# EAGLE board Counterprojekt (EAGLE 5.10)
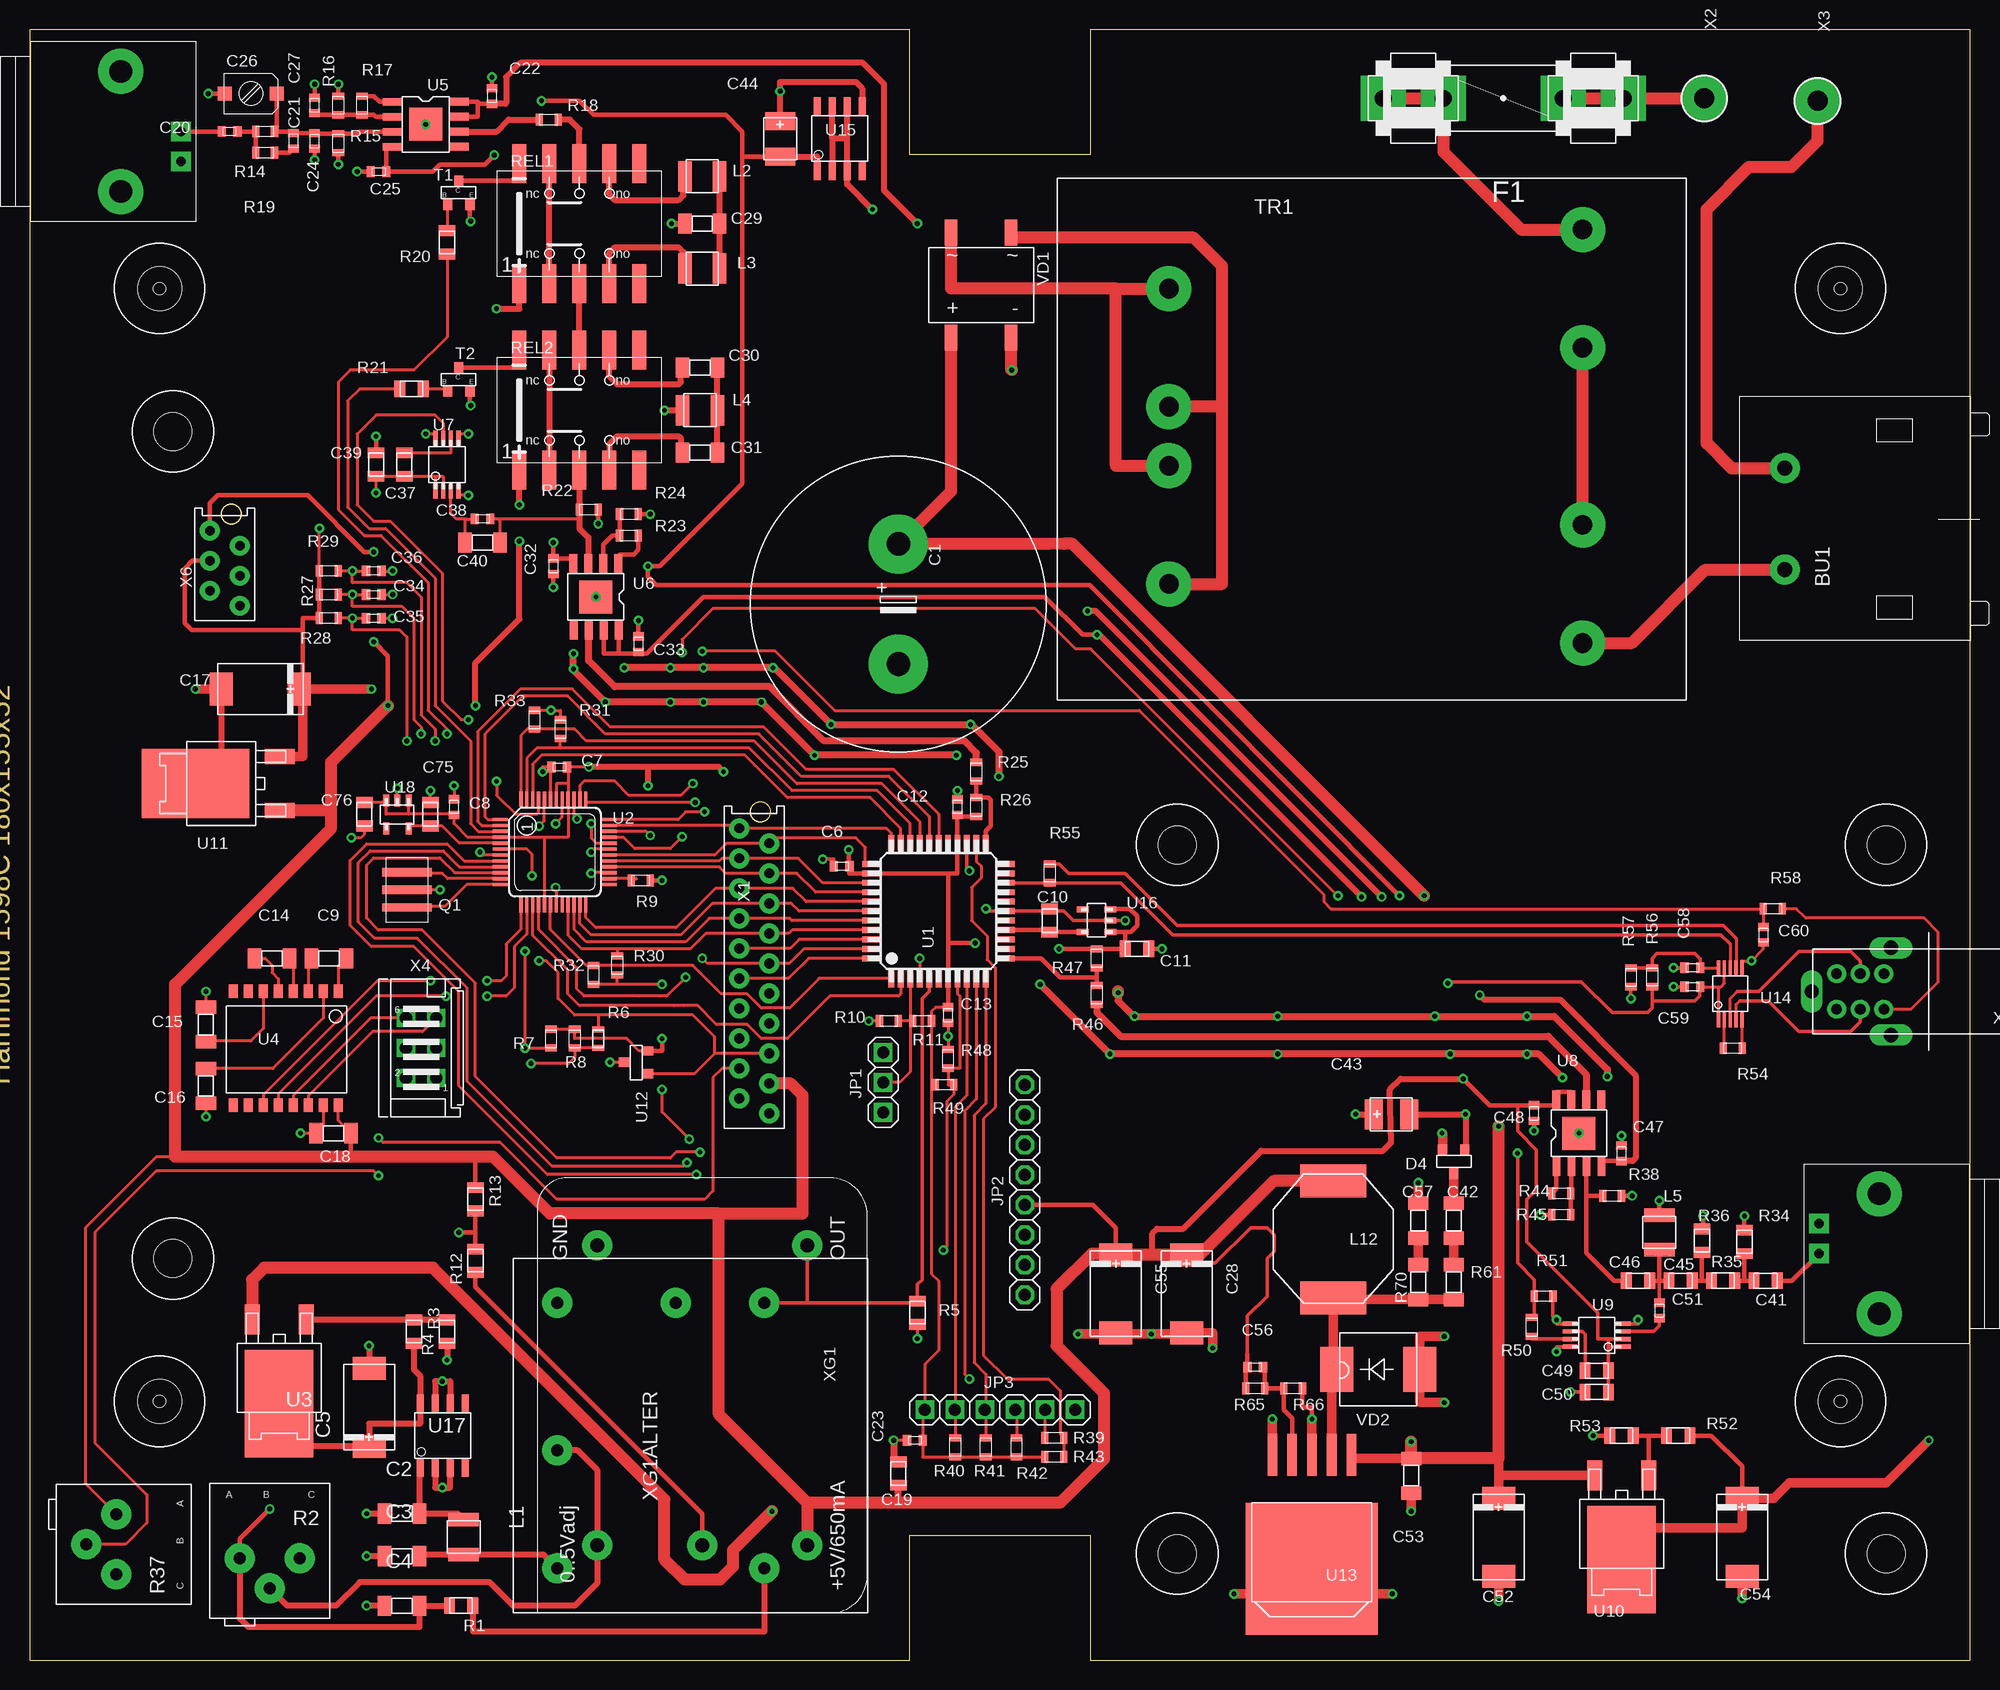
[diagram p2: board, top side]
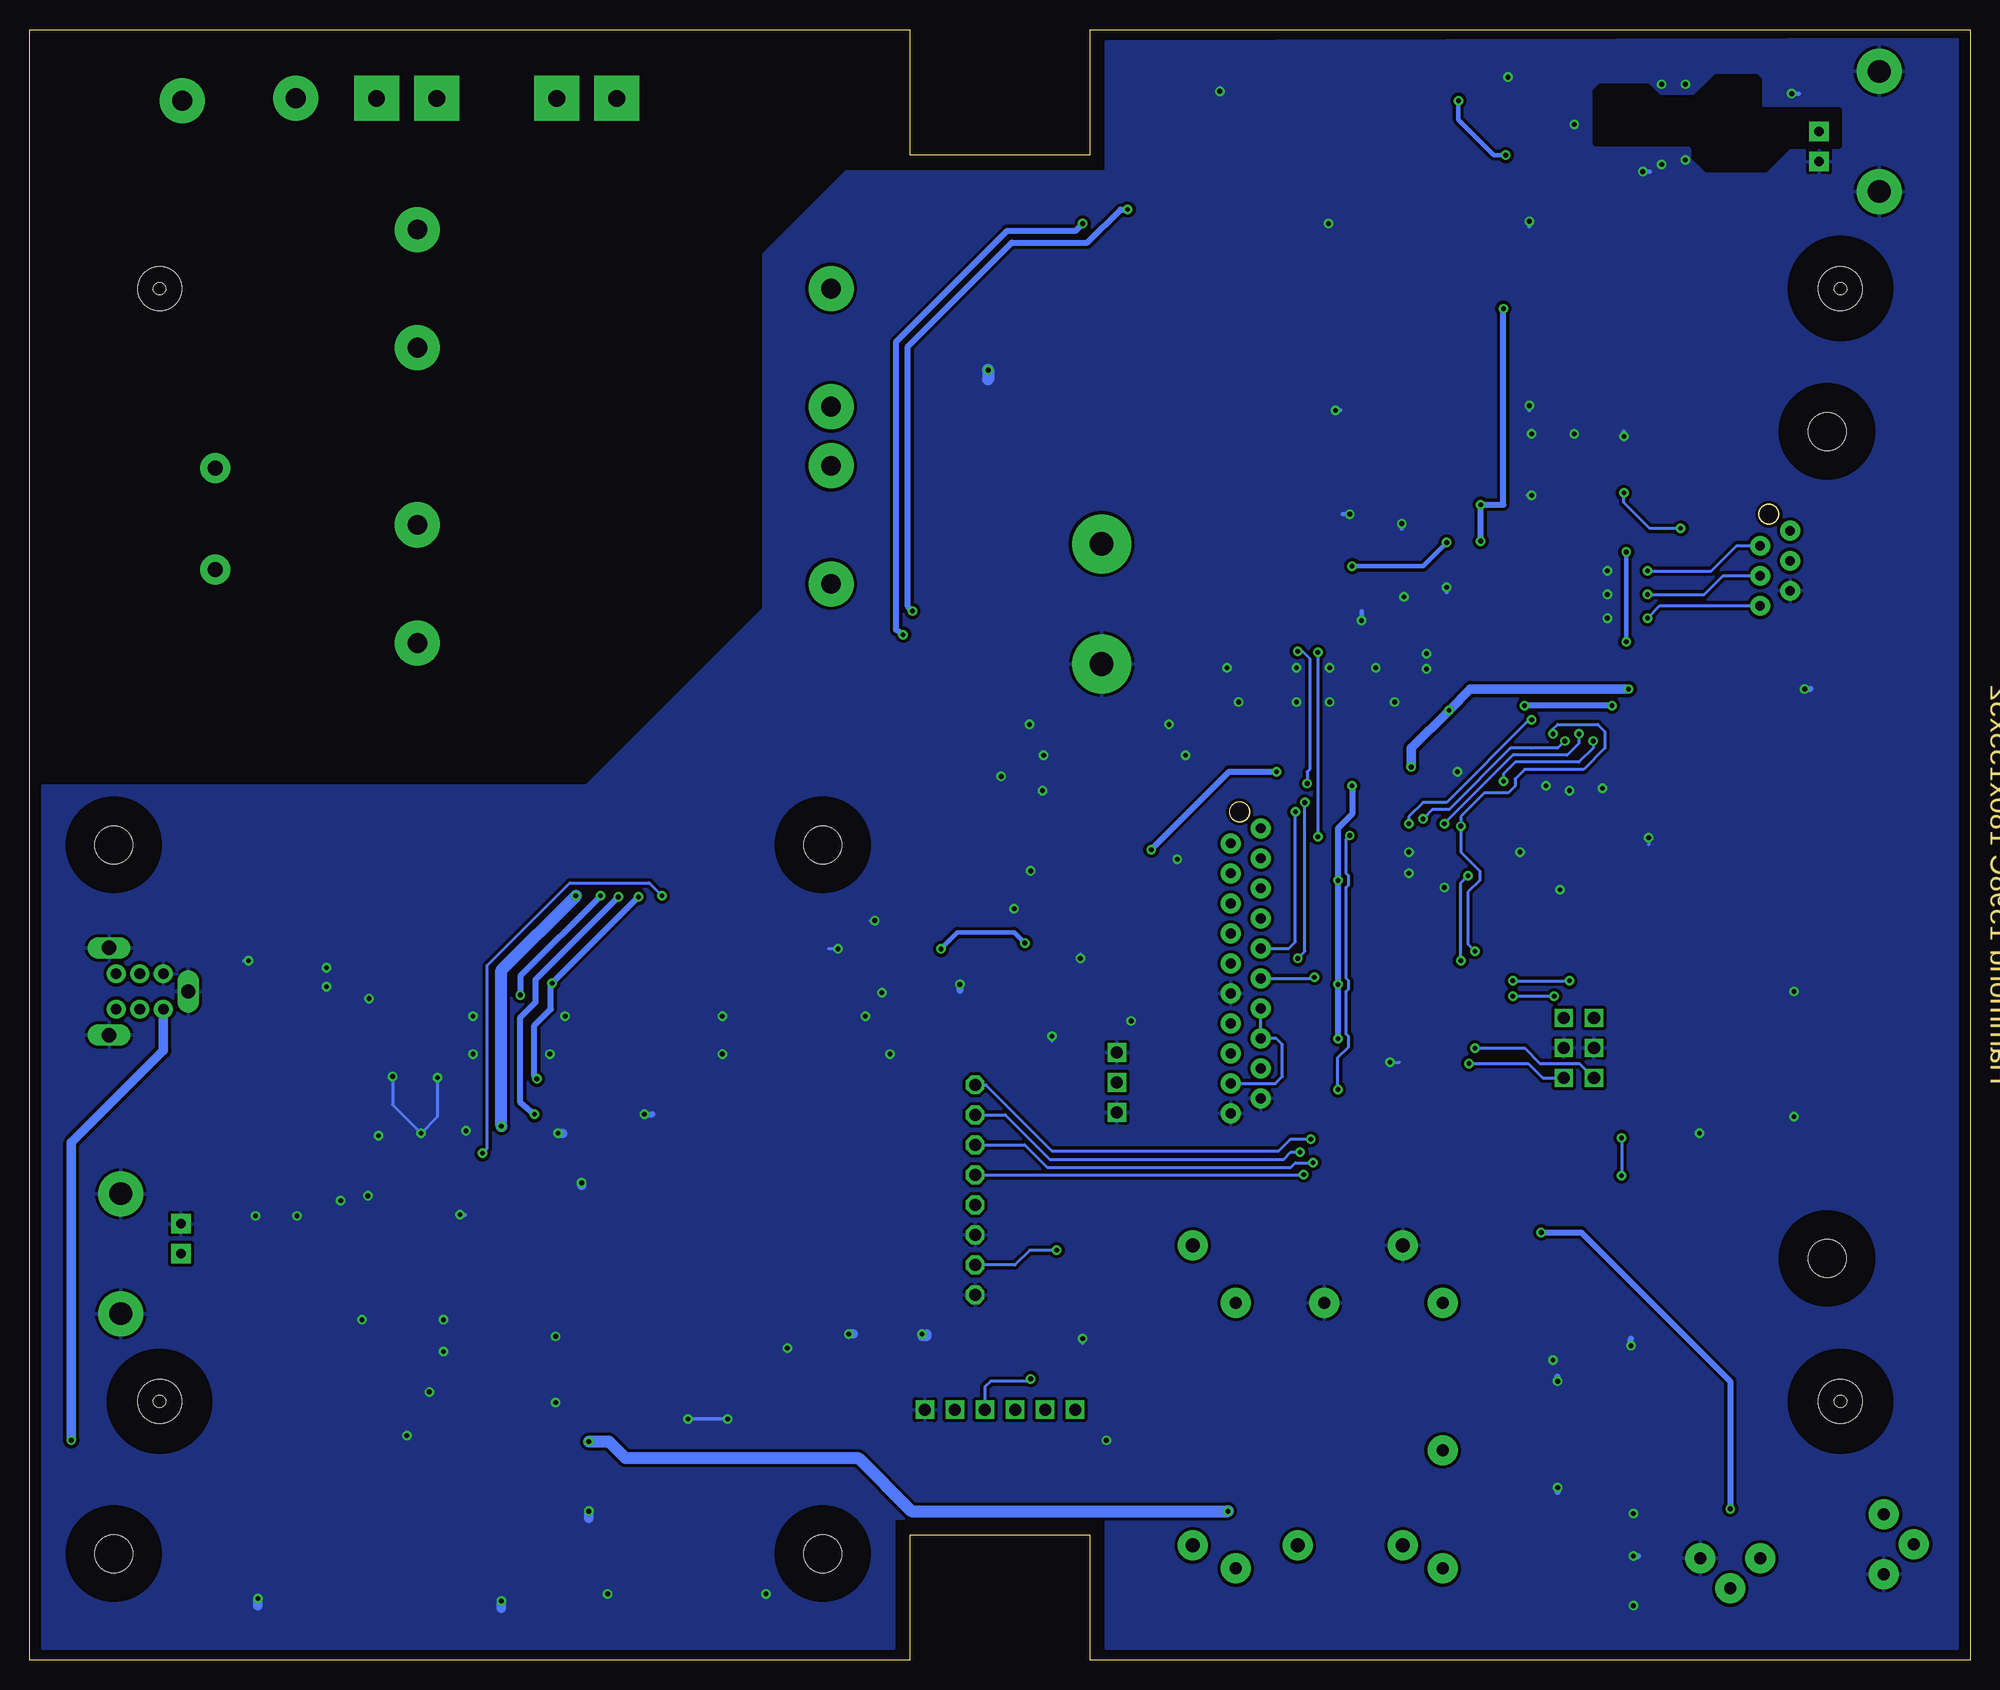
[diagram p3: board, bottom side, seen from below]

Size 164.26 x 138.06 mm. Coordinates in mm from the lower left corner, seen from the top.
Outline: 0,138.06 0,0 74.51,0 74.51,10.61 89.75,10.61 89.75,0 164.26,0 164.26,138.06 89.75,138.06 89.75,127.45 74.51,127.45 74.51,138.06 0,138.06
Copper layers (1*16): Top 0.035mm / dielectric 1.5mm / Bottom 0.035mm
Design rules "alles02": minimum track width 0.2mm, minimum drill 0.4mm, track to track 0.2mm, track to pad 0.2mm, pad to pad 0.2mm, via to via 0.2mm, smd to smd 0mil, copper to edge 0.15mm, drill to drill 0.15mm, minimum pad ring 0.15mm, minimum via ring 0.15mm, stop-mask expansion 4mil, vias tented up to drill 0mil, thermal gap 10mil
bRestrict: 19 lines

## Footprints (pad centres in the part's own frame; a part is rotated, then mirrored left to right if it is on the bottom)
NETZ_BU = drill 1.27 pad 2.54 round: 1 -4.3,0; 2 4.3,0
D25-RM10 = drill 2 pad 5 round: 1 -5.08,0; 2 5.08,0
SOT-1206 = smd 1.143 x 1.702: 1 -1.473,0; 2 1.473,0
TAJ_D = smd 1.93 x 2.794: 1 -3.302,0; 2 3.302,0
SOT-0603 = smd 0.7 x 0.9: 1 -0.66,0; 2 0.66,0
SOT-0805@2 = smd 0.914 x 1.397: 1 -0.991,0; 2 0.991,0
SOT-0805 = smd 0.914 x 1.397: 1 -0.991,0; 2 0.991,0
TZC03 = smd 1.2 x 1.2: 1 -2.2,0; 2 2.2,0
TAJ_B = smd 1.524 x 2.54: 1 -1.46,0; 2 1.524,0
SOT-23 = smd 0.787 x 0.889: 1 -0.94,1.016; 2 0.94,1.016; 3 0,-1.016
DRIL-3,5 = hole 3.708: 0,0 | hole 1.016: 0,0
FUS-HALT = drill 1.422 pad 3.81 square: 1 -10.16,0; 1A -5.08,0; 2 10.16,0; 2A 5.08,0
1X03 = drill 1.016 pad 1.575 square: 1 -2.54,0; 2 0,0; 3 2.54,0
1X08 = drill 1.016 pad 1.575 octagon: 1 -8.89,0; 2 -6.35,0; 3 -3.81,0; 4 -1.27,0; 5 1.27,0; 6 3.81,0; 7 6.35,0; 8 8.89,0
1X06 = drill 1.016 pad 1.575 square: 1 -6.35,0; 2 -3.81,0; 3 -1.27,0; 4 1.27,0; 5 3.81,0; 6 6.35,0
SMD-1210 = smd 1.143 x 2.591: 1 -1.473,0; 2 1.473,0
WE-TPCXL = smd 5.588 x 2.794: 1 0,4.953; 2 0,-4.953
ZTTCV = smd 0.7 x 4.2: 1 -1.5,0; 2 0,0; 3 1.5,0
SMD-0805 = smd 0.914 x 1.397: 1 -0.991,0; 2 0.991,0
RFT-LIEG = drill 1.016 pad 2.54 round: 1 -2.54,0; 2 2.54,0; 3 0,2.54
SMD-0603 = smd 0.508 x 1.016: 1 -0.8,0; 2 0.8,0
SMD-0603' = smd 0.6 x 1: 1 -0.8,0; 2 0.8,0
SMD-0603@1 = smd 0.6 x 1: 1 -0.8,0; 2 0.8,0
SMD-1206 = smd 1.143 x 1.702: 1 -1.473,0; 2 1.473,0
SMD-0603@2 = smd 0.6 x 1: 1 -0.8,0; 2 0.8,0
TQ-RELAI = smd 1.2 x 3.3: 1 -5.08,-5.08; 2 -2.54,-5.08; 3 0,-5.08; 4 2.54,-5.08; 5 5.08,-5.08; 6 5.08,5.08; 7 2.54,5.08; 8 0,5.08; 9 -2.54,5.08; 10 -5.08,5.08
SOT-23' = smd 0.787 x 0.889: 1 0.94,1.016; 2 -0.94,1.016; 3 0,-1.016
HAHN-6VA = drill 1.676 pad 3.81 round: 1 -17.5,-17.5; 2 -17.5,-7.5; 3 -17.5,7.5; 4 -17.5,17.5; 5 17.5,-12.5; 6 17.5,-2.5; 7 17.5,2.5; 8 17.5,12.5
VQ44 = smd 1.5 x 0.5: 1 -5.7,4; 2 -5.7,3.2; 3 -5.7,2.4; 4 -5.7,1.6; 5 -5.7,0.8; 6 -5.7,0; 7 -5.7,-0.8; 8 -5.7,-1.6; 9 -5.7,-2.4; 10 -5.7,-3.2; 11 -5.7,-4; 23 5.7,-4; 24 5.7,-3.2; 25 5.7,-2.4; 26 5.7,-1.6; 27 5.7,-0.8; 28 5.7,0; 29 5.7,0.8; 30 5.7,1.6; 31 5.7,2.4; 32 5.7,3.2; 33 5.7,4 | smd 0.5 x 1.5: 12 -4,-5.7; 13 -3.2,-5.7; 14 -2.4,-5.7; 15 -1.6,-5.7; 16 -0.8,-5.7; 17 0,-5.7; 18 0.8,-5.7; 19 1.6,-5.7; 20 2.4,-5.7; 21 3.2,-5.7; 22 4,-5.7; 34 4,5.7; 35 3.2,5.7; 36 2.4,5.7; 37 1.6,5.7; 38 0.8,5.7; 39 0,5.7; 40 -0.8,5.7; 41 -1.6,5.7; 42 -2.4,5.7; 43 -3.2,5.7; 44 -4,5.7
LQFP48 = smd 0.279 x 1.27: 1 -2.75,-4.5; 2 -2.25,-4.5; 3 -1.75,-4.5; 4 -1.25,-4.5; 5 -0.75,-4.5; 6 -0.25,-4.5; 7 0.25,-4.5; 8 0.75,-4.5; 9 1.25,-4.5; 10 1.75,-4.5; 11 2.25,-4.5; 12 2.75,-4.5; 25 2.75,4.75; 26 2.25,4.75; 27 1.75,4.75; 28 1.25,4.75; 29 0.75,4.75; 30 0.25,4.75; 31 -0.25,4.75; 32 -0.75,4.75; 33 -1.25,4.75; 34 -1.75,4.75; 35 -2.25,4.75; 36 -2.75,4.75 | smd 1.27 x 0.279: 13 4.5,-2.75; 14 4.5,-2.25; 15 4.5,-1.75; 16 4.5,-1.25; 17 4.5,-0.75; 18 4.5,-0.25; 19 4.5,0.25; 20 4.5,0.75; 21 4.5,1.25; 22 4.5,1.75; 23 4.5,2.25; 24 4.5,2.75; 37 -4.5,2.75; 38 -4.5,2.25; 39 -4.5,1.75; 40 -4.5,1.25; 41 -4.5,0.75; 42 -4.5,0.25; 43 -4.5,-0.25; 44 -4.5,-0.75; 45 -4.5,-1.25; 46 -4.5,-1.75; 47 -4.5,-2.25; 48 -4.5,-2.75
DPAK = smd 1.27 x 2.54: 1 -2.286,-2.032; 2 2.286,-2.032 | smd 5.8 x 9.1: 3 0,5.08
SO-16W = smd 0.762 x 1.143: 1 -3.81,-4.826; 2 -2.54,-4.826; 3 -1.27,-4.826; 4 0,-4.826; 5 1.27,-4.826; 6 2.54,-4.826; 7 3.81,-4.826; 8 5.08,-4.826; 9 5.08,4.826; 10 3.81,4.826; 11 2.54,4.826; 12 1.27,4.826; 13 0,4.826; 14 -1.27,4.826; 15 -2.54,4.826; 16 -3.81,4.826
SO-8EXP = smd 0.66 x 1.6: 1 -1.905,-2.819; 2 -0.635,-2.819; 3 0.635,-2.819; 4 1.905,-2.819; 5 1.88,2.819; 6 0.61,2.819; 7 -0.66,2.819; 8 -1.93,2.819 | smd 2.794 x 2.794: GND 0,0
U-SOIC8 = smd 0.356 x 1.219: 1 -0.975,-2.275; 2 -0.325,-2.275; 3 0.325,-2.275; 4 0.975,-2.275; 5 0.975,2.275; 6 0.325,2.275; 7 -0.325,2.275; 8 -0.975,2.275
SOT23 = smd 0.889 x 0.787: 1 -1.016,0.965; 2 -1.016,-0.965; 3 1.016,0
TO263-5L = smd 0.813 x 3.556: 1 -3.353,-8.382; 2 -1.676,-8.382; 3 0,-8.382; 4 1.676,-8.382; 5 3.353,-8.382 | smd 11.176 x 11.176: 6 0,1.27
RM-10 = smd 0.279 x 1.27: 1 -1,-2.2; 2 -0.5,-2.2; 3 0,-2.2; 4 0.5,-2.2; 5 1,-2.2; 6 1,2.2; 7 0.5,2.2; 8 0,2.2; 9 -0.5,2.2; 10 -1,2.2
SO-8 = smd 0.61 x 1.524: 1 -1.27,-2.743; 2 0,-2.743; 3 1.27,-2.743; 4 2.54,-2.743; 5 2.54,2.743; 6 1.27,2.743; 7 0,2.743; 8 -1.27,2.743
SOT-23-5 = smd 0.508 x 1.016: 1 -0.953,-1.143; 2 0,-1.143; 3 0.953,-1.143; 4 0.953,1.206; 5 -0.953,1.206
DRIL-3 = hole 3.2: 0,0
DBS15X = smd 1.067 x 2.184: AC1 -2.54,-4.445; AC2 2.54,-4.445; MI -2.54,4.445; PL 2.54,4.445
SMC = smd 2.794 x 3.81: A 3.505,0; K -3.505,0
MIMA20 = drill 0.813 pad 1.676 round: 1 0,1.27; 2 -1.27,-1.27; 3 -2.54,1.27; 4 -3.81,-1.27; 5 -5.08,1.27; 6 -6.35,-1.27; 7 -7.62,1.27; 8 -8.89,-1.27; 9 -10.16,1.27; 10 -11.43,-1.27; 11 -12.7,1.27; 12 -13.97,-1.27; 13 -15.24,1.27; 14 -16.51,-1.27; 15 -17.78,1.27; 16 -19.05,-1.27; 17 -20.32,1.27; 18 -21.59,-1.27; 19 -22.86,1.27; 20 -24.13,-1.27 | hole 1.676: 1.4,-0.53
LÖTÖSE = drill 1.702 pad 3.81 round: 1 0,0
LUMBG6 = drill 1.016 pad 1.422 square: 1 -1.27,2.54; 2 1.27,2.54; 3 -1.27,0; 4 1.27,0; 5 -1.27,-2.54; 6 1.27,-2.54
BNC = drill 1.93 pad 3.81 round: G1 0,5.08; G2 0,-5.08 | drill 0.813 pad 1.676 square: G3 -5.08,2.54; SIG -5.08,0
MIMA6 = drill 0.813 pad 1.676 round: 1 0,1.27; 2 -1.27,-1.27; 3 -2.54,1.27; 4 -3.81,-1.27; 5 -5.08,1.27; 6 -6.35,-1.27 | hole 1.676: 1.4,-0.53
IEEE1394-6V = drill 0.9 pad 1.6 round: 1 4,1.5; 2 4,-1.5; 3 2,1.5; 4 2,-1.5; 5 0,1.5; 6 0,-1.5 | drill 1.2 long: G1 6.1,0; G2 -0.6,3.7; G3 -0.6,-3.7
TXCO-4 = drill 1.016 pad 2.54 round: 1 -11.25,6.25; 2 -11.25,-1.25; 3 -11.25,-11.25; 4 1.25,-11.25; 5 11.25,-11.25; 6 11.25,6.25
OCXO_ISOT = drill 1.2 pad 2.54 round: 1 -12.7,8.89; 2 -12.7,0; 3 -12.7,-8.89; 4 12.7,-8.89; 5 12.7,8.89

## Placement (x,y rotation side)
BU1  [NETZ_BU]  148.53,96.63 90 top
C1  2200/50  [D25-RM10]  73.53,89.43 270 top
C2  10uF  [SOT-1206]  31.53,12.43 0 top
C3  10uF  [SOT-1206]  31.53,8.83 0 top
C4  10uF  [SOT-1206]  31.53,4.63 0 top
C5  100/16  [TAJ_D]  28.73,21.43 90 top
C6  100nF  [SOT-0603]  68.73,67.23 0 top
C7  100nF  [SOT-0603]  44.83,75.63 0 top
C8  100nF  [SOT-0603]  35.93,72.23 270 top
C9  10uF  [SOT-1206]  25.33,59.43 180 top
C10  1uF  [SOT-0805@2]  86.33,62.63 270 top
C11  1uF  [SOT-0805@2]  93.73,60.23 180 top
C12  100nF  [SOT-0603]  78.53,72.23 270 top
C13  100nF  [SOT-0603]  77.73,54.63 90 top
C14  10uF  [SOT-1206]  20.53,59.43 180 top
C15  10uF  [SOT-1206]  14.93,53.83 270 top
C16  10uF  [SOT-1206]  14.93,48.63 90 top
C17  100uF/10  [TAJ_D]  19.53,82.23 180 top
C18  10uF  [SOT-1206]  25.73,44.63 0 top
C19  [SOT-0805]  73.53,15.83 270 top
C20  100nF  [SOT-0603]  16.93,129.43 180 top
C21  15pF  [SOT-0603]  22.33,128.63 270 top
C22  100nF  [SOT-0603]  39.13,132.43 270 top
C23  100nF  [SOT-0603]  74.93,18.63 0 top
C24  ?  [SOT-0603]  24.13,128.63 90 top
C25  100nF  [SOT-0603]  29.53,126.03 0 top
C26  TZC03  [TZC03]  18.73,132.63 180 top
C27  2.2pF  [SOT-0603]  24.13,131.63 270 top
C28  220uF/10  [TAJ_D]  97.93,31.03 270 top
C29  33nF  [SOT-1206]  56.93,121.63 0 top
C30  33nF  [SOT-1206]  56.73,109.43 180 top
C31  33nF  [SOT-1206]  56.73,102.23 180 top
C32  100nF  [SOT-0603]  44.33,92.63 90 top
C33  100nF  [SOT-0603]  51.53,86.03 270 top
C34  [SOT-0603]  29.13,90.23 180 top
C35  [SOT-0603]  29.13,88.23 180 top
C36  [SOT-0603]  29.13,92.23 180 top
C37  1uF  [SOT-0805]  31.73,101.23 270 top
C38  1nF  [SOT-0603]  38.33,96.63 0 top
C39  1uF  [SOT-0805]  29.33,101.23 270 top
C40  10uF  [SOT-1206]  38.33,94.63 0 top
C41  1uF  [SOT-0805]  146.93,32.13 0 top
C42  1uF  [SOT-1206]  120.53,37.23 90 top
C43  10uF/16  [TAJ_B]  115.23,46.23 0 top
C44  10uF/16  [TAJ_B]  63.53,128.83 270 top
C45  [SOT-0805]  139.73,32.13 0 top
C46  [SOT-0805]  136.13,32.13 0 top
C47  100nF  [SOT-0603]  134.73,42.93 270 top
C48  100nF  [SOT-0603]  127.33,46.33 90 top
C49  1uF  [SOT-0805]  132.63,24.53 0 top
C50  1uF  [SOT-0805]  132.63,22.73 0 top
C51  100nF  [SOT-0603]  137.93,29.63 90 top
C52  22/25  [TAJ_D]  124.33,10.43 270 top
C53  100nF  [SOT-1206]  116.93,15.63 90 top
C54  22/25  [TAJ_D]  144.93,10.43 270 top
C55  220uF/10  [TAJ_D]  91.93,31.03 270 top
C56  10nF  [SOT-0603]  103.73,24.83 180 top
C57  4n7  [SOT-1206]  117.53,37.23 270 top
C58  [SOT-0603]  140.73,58.63 0 top
C59  [SOT-0603]  140.73,57.03 0 top
C60  [SOT-0603]  146.73,61.43 90 top
C75  1uF  [SOT-0805@2]  33.93,71.63 270 top
C76  1uF  [SOT-0805@2]  28.33,71.63 90 top
D4  BAR-43-S  [SOT-23]  120.53,42.23 0 top
E$1  [DRIL-3,5]  153.25,116.13 0 top
E$2  [DRIL-3,5]  153.25,21.93 0 top
E$3  [DRIL-3,5]  11,21.93 0 top
E$4  [DRIL-3,5]  11,116.13 0 top
F1  [FUS-HALT]  124.73,132.23 180 top
JP1  Eingang 5  [1X03]  72.23,48.93 90 top
JP2  [1X08]  84.23,39.83 90 top
JP3  PINHD-1X6  [1X06]  82.13,21.23 0 top
L1  47uH  [SMD-1210]  36.73,10.43 270 top
L2  33uH  [SMD-1210]  56.93,125.63 0 top
L3  33uH  [SMD-1210]  56.93,117.83 0 top
L4  33uH  [SMD-1210]  56.73,105.83 180 top
L5  [SMD-1210]  137.93,36.23 270 top
L12  WE-TPCXL  [WE-TPCXL]  110.33,35.63 180 top
Q1  [ZTTCV]  31.93,65.23 270 top
R1  39k  [SMD-0805]  36.53,4.63 180 top
R2  4k7  [RFT-LIEG]  20.33,8.63 180 top
R3  [SMD-0805]  32.53,27.83 270 top
R4  [SMD-0805]  35.33,27.83 90 top
R5  2k7  [SMD-0805]  75.13,29.43 90 top
R6  330  [SMD-0603]  48.13,52.63 270 top
R7  2k2  [SMD-0603']  44.13,52.63 90 top
R8  4k7  [SMD-0603']  46.13,52.63 90 top
R9  [SMD-0603']  51.73,66.03 180 top
R10  [SMD-0603']  72.73,54.13 180 top
R11  [SMD-0603']  75.53,54.13 0 top
R12  [SMD-0805]  37.73,33.83 90 top
R13  [SMD-0805]  37.73,39.03 270 top
R14  180k  [SMD-0603']  19.93,129.43 180 top
R15  820k  [SMD-0603']  26.13,128.43 90 top
R16  470  [SMD-0603']  26.13,131.63 270 top
R17  470  [SMD-0603']  28.13,131.63 270 top
R18  10  [SMD-0603']  43.93,130.43 180 top
R19  470  [SMD-0603']  19.93,127.63 180 top
R20  22k  [SMD-0805]  35.33,120.03 270 top
R21  22k  [SMD-0805]  32.33,107.63 180 top
R22  [SMD-0603']  47.33,97.43 180 top
R23  [SMD-0603']  50.73,95.23 180 top
R24  [SMD-0603']  50.73,97.03 0 top
R25  [SMD-0603']  80.13,75.23 90 top
R26  [SMD-0603']  80.13,72.23 90 top
R27  [SMD-0603']  25.33,90.23 180 top
R28  [SMD-0603']  25.33,88.23 180 top
R29  [SMD-0603']  25.33,92.23 180 top
R30  3k3  [SMD-0603']  49.73,58.83 270 top
R31  3k3  [SMD-0603']  44.93,78.83 90 top
R32  3k3  [SMD-0603']  47.73,58.03 270 top
R33  3k3  [SMD-0603']  42.73,79.63 90 top
R34  [SMD-0805]  145.13,35.43 270 top
R35  [SMD-0805]  143.33,32.13 0 top
R36  [SMD-0805]  141.53,35.53 270 top
R37  [RFT-LIEG]  7.33,9.83 90 top
R38  68  [SMD-0603']  133.93,39.33 180 top
R39  33  [SMD-0603@1]  86.73,18.83 180 top
R40  2k7  [SMD-0603@1]  78.33,18.03 270 top
R41  2k7  [SMD-0603@1]  80.93,18.03 270 top
R42  2k7  [SMD-0603@1]  83.53,18.03 270 top
R43  2k7  [SMD-0603@1]  86.73,17.23 180 top
R44  [SMD-0603']  129.63,39.53 0 top
R45  [SMD-0603']  129.63,37.73 180 top
R46  [SMD-0603']  90.33,56.33 270 top
R47  [SMD-0603']  90.33,59.43 270 top
R48  [SMD-0603']  77.73,50.93 270 top
R49  [SMD-0603']  77.43,48.73 0 top
R50  22k  [SMD-0603']  127.13,28.23 90 top
R51  33k  [SMD-0603']  128.13,30.83 180 top
R52  [SMD-0805]  139.53,19.03 0 top
R53  [SMD-0805]  134.73,19.03 0 top
R54  [SMD-0603']  144.13,51.83 180 top
R55  [SMD-0603']  86.33,66.63 270 top
R56  [SMD-0603']  137.33,57.83 270 top
R57  [SMD-0603']  135.53,57.83 90 top
R58  [SMD-0603']  147.53,63.63 0 top
R61  2R2  [SMD-1206]  120.53,32.03 90 top
R65  3k9  [SMD-0603@2]  103.73,23.03 180 top
R66  1k3  [SMD-0603@2]  106.93,23.03 180 top
R70  330  [SMD-1206]  117.53,32.03 270 top
REL1  [TQ-RELAI]  46.53,121.63 0 top
REL2  [TQ-RELAI]  46.53,105.83 0 top
T1  [SOT-23']  36.33,124.23 180 top
T2  [SOT-23']  36.33,108.43 180 top
TR1  [HAHN-6VA]  113.93,103.63 180 top
U1  [VQ44]  76.93,63.43 90 top
U2  LPC2103  [LQFP48]  44.33,68.43 270 top
U3  LM1117ADJ  [DPAK]  21.13,26.83 180 top
U4  [SO-16W]  22.33,51.83 180 top
U5  ADA4817  [SO-8EXP]  33.53,130.03 270 top
U6  AD8000  [SO-8EXP]  47.93,90.03 180 top
U7  AD8361  [U-SOIC8]  35.33,101.23 0 top
U8  AD8000  [SO-8EXP]  131.13,44.63 0 top
U9  AD8361  [U-SOIC8]  132.63,27.53 90 top
U10  [DPAK]  134.73,13.63 180 top
U11  LF-33  [DPAK]  19.13,74.23 90 top
U12  MCP100T-300  [SOT23]  51.33,50.63 180 top
U13  TS2596CM5  [TO263-5L]  108.53,9.03 180 top
U14  AD8351  [RM-10]  143.93,56.43 0 top
U15  TS79L05CS  [SO-8]  67.93,128.83 0 top
U16  LP5951MF-1.8  [SOT-23-5]  90.33,62.63 90 top
U17  78L09  [SO-8]  34.33,19.03 0 top
U18  LP5951MF-1.8  [SOT-23-5]  31.13,71.63 180 top
U$69  [DRIL-3]  12.13,104.03 0 top
U$70  [DRIL-3]  12.13,34.03 0 top
U$71  [DRIL-3]  157.13,69.03 0 top
U$72  [DRIL-3]  157.13,9.03 0 top
U$73  [DRIL-3]  97.13,9.03 0 top
U$74  [DRIL-3]  97.13,69.03 0 top
VD1  DBS15X  [DBS15X]  80.53,116.43 180 top
VD2  MBRS340T3  [SMC]  114.13,24.63 0 top
X1  [MIMA20]  61.33,70.43 90 top
X2  [LÖTÖSE]  141.73,132.23 270 top
X3  [LÖTÖSE]  151.33,132.03 270 top
X4  Prog  [LUMBG6]  33.13,51.83 180 top
X5  [BNC]  7.73,129.43 180 top
X6  Drehgeber Anschluss  [MIMA6]  16.53,95.63 90 top
X7  [BNC]  156.53,34.43 0 top
X8  FIREWIRE6  [IEEE1394-6V]  156.93,56.63 180 top
XG1  [TXCO-4]  55.93,19.03 270 top
XG1ALTER  OCXO_ISOT  [OCXO_ISOT]  56.93,22.43 90 top

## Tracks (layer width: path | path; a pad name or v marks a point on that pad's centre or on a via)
+3,3V  (via drill 0.4 pad 0.8)
  Top 0.25: R43.2 R42.2 R41.2 R40.2 75.59,17.23 C23.2 75.59,21.23 JP3.1 75.78,25.08 76.93,26.23 76.93,32.13 76.33,32.73 76.33,48.73 | 43.58,69.68 U2.4 37.08,69.68 35.93,70.83 C8.2 35.87,71.63 32.08,71.63 | 43.58,69.68 U2.17 | 43.58,69.68 45.58,69.68 U2.40 45.58,74.23 | 91.52,63.63 U16.3 | C6.2 69.33,67.29 | v47.33,75.63 C7.2 45.58,75.63 45.58,74.23 | 32.08,71.63 U18.1 | 32.08,71.63 30.18,71.63 U18.3 30.18,72.62 C76.2 | U12.2 51.56,51.59 50.53,52.63 46.13,52.63 R8.2 R7.2 | 76.33,48.73 R11.2 76.33,54.93 76.69,55.29 C13.2 | U2.42 44.58,74.23 45.58,74.23 | R31.2 44.93,80.43 v44.13,80.43 R33.2 | 49.73,57.23 R32.2 | 49.73,57.23 R30.2 | v53.53,57.23 49.73,57.23 | U7.2 35,100.24 34.35,100.24 | 34.35,100.24 U7.1 | 34.35,100.24 C37.2 C39.2 v29.33,98.83 | R29.2 v24.53,95.83 | 76.33,48.73 R49.1
  Top 0.4: U1.35 78.53,66.63 U1.26 C12.2 78.67,71.43 R26.1 | U1.35 77.73,66.63 77.73,60.73 | v80.03,60.73 77.73,60.73 | 77.73,60.73 U1.7 C13.2 | U1.35 69.39,66.63 C6.2 | 92.63,61.68 93.18,61.68 93.73,62.23 93.73,63.03 93.13,63.63 91.52,63.63 | 92.63,61.68 U16.1 | 69.33,67.29 v69.33,68.63 | v53.53,66.03 R9.1 | U12.2 53.49,51.59 53.53,51.63 v53.53,52.63 | v87.13,60.23 R47.1 C11.2 92.74,61.57 92.63,61.68 | 23.13,82.23 23.13,87.23 | 23.13,87.23 23.13,88.23 R28.2 R27.2 R29.2 | X6.3 13.79,93.09 13.13,92.43 13.13,87.83 13.73,87.23 23.13,87.23
  Top 0.5: v58.73,75.23 58.33,75.63 52.33,75.63 | 52.33,75.63 v52.33,74.03 | 52.33,75.63 v47.33,75.63
  Top 0.8: v28.93,82.23 23.13,82.23 | 23.13,82.23 C17.1 | U11.2 23.13,76.52 23.13,82.23
  Bottom 0.25: v29.33,98.83 29.33,98.03 27.13,95.83 v24.53,95.83
  Bottom 0.4: v80.03,60.73 80.93,61.63 85.73,61.63 v87.13,60.23
  Bottom 0.5: v69.33,68.63 62.73,75.23 v58.73,75.23 | v52.33,74.03 52.33,71.63 53.53,70.43 v53.53,66.03 v53.53,57.23 v53.53,52.63
  Bottom 0.8: v28.93,82.23 42.33,82.23 v44.13,80.43 47.33,77.23 v47.33,75.63
+5V  (via drill 0.4 pad 0.8)
  Top 0.25: U4.16 26.14,45.69 C18.2 | 25.53,72.03 25.44,71.94 | 12.33,42.63 10.73,42.63 4.73,36.63 4.73,14.97 R37.2 | U14.9 143.43,57.33 143.13,57.03 142.93,57.03 | C59.2 142.93,57.03 | 142.93,57.03 U14.1
  Top 0.3: 103.07,25.97 103.07,29.17 104.73,30.83 104.73,34.03 105.33,34.63 105.33,36.03 104.73,36.63 103.33,36.63 100.33,33.63 97.93,33.63 C28.1 | 133.53,27.2 132.73,27.2 132.73,29.43 126.73,35.43 126.73,39.03 127.53,39.83 127.53,43.23 125.93,44.83 125.93,46.99 | 133.53,27.2 U9.2 | 133.62,26.43 133.62,27.11 133.53,27.2 | 133.62,26.43 C49.2 C50.2 | U9.1 133.75,26.55 133.62,26.43 | C59.2 141.33,56.97 141.33,56.23 140.93,55.83 137.33,55.83 | v120.03,57.33 120.13,57.43 131.33,57.43 133.93,54.83 136.93,54.83 137.33,55.23 137.33,55.83 | 137.33,55.83 R56.2
  Top 0.4: 27.2,42.63 C18.2 | U5.7 37.93,130.69 37.93,131.77 | U5.8 37.93,131.96 37.93,131.77 | C22.2 37.93,131.77 | R65.2 102.93,24.69 C56.2 103.07,25.97 | U6.7 48.59,85.23 49.86,85.23 | 49.86,85.23 U6.8 | 49.86,85.23 51.53,85.23 C33.2 51.59,85.43 51.59,85.23 52.23,85.23 57.03,90.03 85.93,90.03 89.13,86.83 v90.33,86.83 | 37.73,42.63 R13.1 | v30.33,80.83 30.33,85.03 v29.13,86.23 | v29.13,93.83 28.33,93.83 23.53,98.63 15.93,98.63 15.26,97.96 X6.1 | U8.7 130.47,48.13 129.2,48.13 U8.8 129.2,46.99 C48.2 125.93,46.99 123.57,46.99 v121.33,49.23 | JP2.4 90,38.56 91.93,36.63 C55.1
  Top 0.5: v112.73,64.63 90.53,86.83 v90.33,86.83 | v75.13,121.63 72.33,124.43 72.33,133.43 70.53,135.23 41.53,135.23 40.33,134.03 40.33,131.83 40.27,131.77 C22.2 | REL1.1 41.45,114.43 v39.53,114.43 | v41.45,97.83 REL2.1 | v37.73,80.83 37.73,84.43 41.45,88.15 v41.45,94.75 | v121.33,49.23 116.03,49.23 115.13,48.33 115.23,43.83 114.53,43.13 104.23,43.13 97.63,36.53 95.43,36.53 95.03,36.13 95.03,34.33
  Top 0.6: 73.53,13.34 C19.2
  Top 0.8: C55.1 91.93,33.83
  Top 1: 58.33,37.83 44.03,37.83 39.23,42.63 37.73,42.63 27.2,42.63 12.33,42.63 12.33,57.23 25.53,70.43 25.53,72.03 25.53,76.03 v30.33,80.83 | X1.18 64.42,48.84 65.43,47.83 65.43,37.83 58.33,37.83 | 65.82,13.34 XG1ALTER.3 | 65.82,13.34 58.33,20.83 58.33,37.83 | 65.82,13.34 73.53,13.34 87.24,13.34 90.93,17.03 90.93,22.63 86.93,26.63 86.93,31.43 89.93,34.43 91.83,34.43 C55.1 95.03,34.33 C28.1 98.03,34.43 99.13,34.43 105.28,40.58 L12.2 | 25.44,71.94 U11.1
  Bottom 0.25: X1.13 X1.15 58.75,52.65 58.23,52.13 58.23,49.43 58.82,48.84 X1.18
  Bottom 0.4: v29.13,86.23 v29.13,93.83
  Bottom 0.5: v121.33,49.23 121.53,49.43 121.53,53.73 120.13,55.13 120.13,57.23 v120.03,57.33 v112.73,64.63 | v90.33,86.83 90.93,87.23 90.93,111.63 81.53,121.03 75.73,121.03 v75.13,121.63 | v30.33,80.83 v37.73,80.83 | v39.53,114.43 39.53,97.83 v41.45,97.83 v41.45,94.75
+12EXT  (via drill 0.4 pad 0.8)
  Top 0.4: C54.1 144.93,16.43 142.33,19.03 R52.2
  Top 0.8: U10.3 134.73,11.23 144.93,11.23 C54.1 147.63,13.73 148.93,15.03 157.13,15.03 v160.73,18.63
  Bottom 0.8: X8.1 152.93,51.63 160.73,43.83 v160.73,18.63
+12V  (via drill 0.4 pad 0.8)
  Top 0.8: U13.1 111.88,17.1 C53.2 | 124.33,15.66 124.33,17.1 | U10.2 124.33,15.66 | 124.33,15.66 C52.1
  Top 1: U3.2 18.84,32.23 19.84,33.23 34.13,33.23 53.73,13.63 53.73,8.53 55.43,6.83 58.43,6.83 59.53,7.93 59.53,9.33 v62.83,12.63 | VD1.PL 77.99,98.97 C1.1 86.25,94.51 87.53,94.53 88.23,94.53 v118.03,64.73 | v124.33,45.23 124.33,17.1 C53.2 v116.93,18.53
  Bottom 1: v124.33,45.23 124.33,58.43 v118.03,64.73 | v116.93,18.53 115.23,18.53 113.83,17.13 94.13,17.13 89.63,12.63 v62.83,12.63
-5V  (via drill 0.4 pad 0.8)
  Top 0.4: U5.4 30.19,128.12 C25.2 34.13,126.03 34.73,126.63 38.53,126.63 v39.33,127.43 | v44.33,94.63 C32.2 46.02,93.29 U6.4 | v43.33,132.03 46.53,132.03 47.73,130.83 58.93,130.83 60.33,129.43 60.33,127.31 | 60.33,127.31 60.33,99.63 53.33,92.63 v52.33,92.63 52.33,91.73 53.03,91.03 89.73,91.03 90.73,90.03 v115.93,64.73 | 60.33,127.31 C44.2 | U8.4 133.03,42.27 C47.2
  Top 0.5: U15.1 66.66,127.31 C44.2 arc-90 63.45,127.23 | C47.2 135.67,42.27 135.93,42.53 135.93,49.53 129.53,55.93 123.13,55.93 v122.73,56.33
  Bottom 0.4: v44.33,94.63 46.33,92.63 v52.33,92.63 | v39.33,127.43 40.33,127.43 43.33,130.43 v43.33,132.03
  Bottom 0.5: v122.73,56.33 122.73,57.93 v115.93,64.73
/RESET  (via drill 0.4 pad 0.8)
  Top 0.25: X1.16 57.98,51.38 | v42.53,66.43 42.53,68.23 42.08,68.68 U2.6 | v43.13,59.23 43.73,59.23 44.73,58.23 44.73,56.03 46.13,54.63 48.13,54.63 | 48.13,54.63 R6.1 | 48.13,54.63 56.13,54.63 57.98,52.78 57.98,51.38 | U12.1 56.27,49.67 57.98,51.38
  Bottom 0.25: v43.13,59.23 43.13,65.83 v42.53,66.43
A0  (via drill 0.4 pad 0.8)
  Top 0.25: X1.11 64.23,57.73 65.93,59.43 U1.44 | U2.16 43.08,61.88 46.33,58.63 46.33,56.83 46.93,56.23 51.53,56.23 53.33,56.23 53.93,56.23 v55.53,57.83
  Bottom 0.25: X1.11 55.63,57.73 v55.53,57.83
A1
  Top 0.25: U2.15 42.58,61.38 45.53,58.43 45.53,56.43 46.53,55.43 54.53,55.43 55.33,55.43 56.53,55.43 58.13,53.83 60.73,53.83 61.93,52.63 64.13,52.63 67.73,56.23 73.53,56.23 73.73,56.43 U1.2
COUNT_CAP0.0
  Top 0.25: U2.18 44.08,61.88 47.13,58.83 R32.1 56.13,58.83 58.53,56.43 60.73,56.43 61.93,55.23 64.33,55.23 66.83,57.73 U1.1
D0
  Top 0.25: U1.41 64.53,61.83 64.24,61.54 X1.8 57.24,61.54 55.93,60.23 49.73,60.23 | U2.21 45.58,61.38 46.73,60.23 49.73,60.23 | 49.73,60.23 R30.1
D1
  Top 0.25: U1.40 64.53,62.63 64.35,62.81 X1.7 57.51,62.81 55.53,60.83 47.13,60.83 46.08,61.88 U2.22
D2
  Top 0.25: U1.39 65.13,63.43 64.48,64.08 X1.6 57.78,64.08 55.13,61.43 47.53,61.43 46.58,62.38 U2.23
D3
  Top 0.25: U1.38 65.73,64.23 64.61,65.35 X1.5 58.05,65.35 54.73,62.03 47.93,62.03 47.08,62.88 U2.24
D4
  Top 0.25: U1.37 66.53,65.03 64.94,66.62 X1.4 58.94,66.62 58.38,67.18 U2.28
D5
  Top 0.25: U1.36 67.13,65.83 65.07,67.89 X1.3 58.59,67.89 58.38,67.68 U2.29
D6
  Top 0.25: U1.34 70.73,67.43 70.73,68.83 69.93,69.63 63.07,69.63 X1.2 58.96,69.16 57.98,68.18 U2.30
D7
  Top 0.25: U1.33 72.93,70.03 72.53,70.43 X1.1 59.81,70.68 U2.35
DG_DIR  (via drill 0.4 pad 0.8)
  Top 0.25: U2.41 45.08,71.38 v44.53,70.83 | v33.13,78.43 33.13,79.03 32.53,79.63 32.53,88.23 31.53,89.23 27.33,89.23 v27.33,90.23 | v27.33,90.23 R27.1 | v27.33,90.23 C34.2
  Bottom 0.25: v44.53,70.83 38.73,76.63 34.13,76.63 33.73,77.03 33.13,77.63 v33.13,78.43 | X6.4 20.94,91.82 22.53,90.23 v27.33,90.23
DG_INT  (via drill 0.4 pad 0.8)
  Top 0.25: U2.45 43.08,71.78 42.93,71.63 41.13,71.63 39.53,73.23 v39.53,74.43 | v31.93,77.83 31.93,86.63 31.33,87.23 27.33,87.23 v27.33,88.23 | v27.33,88.23 C35.2 | v27.33,88.23 R28.1
  Bottom 0.25: v39.53,74.43 39.53,75.03 38.53,76.03 33.13,76.03 31.93,77.23 v31.93,77.83 | X6.6 26.28,89.28 v27.33,88.23
DG_TAST  (via drill 0.4 pad 0.8)
  Top 0.25: U2.39 46.08,71.48 v46.33,71.23 | v34.33,77.83 34.33,78.83 33.13,80.03 33.13,90.03 31.93,91.23 27.33,91.23 v27.33,92.23 | v27.33,92.23 C36.2 | v27.33,92.23 R29.1
  Bottom 0.25: v46.33,71.23 45.53,72.03 44.13,72.03 38.93,77.23 37.13,77.23 34.93,77.23 v34.33,77.83 | X6.2 19.8,94.36 21.93,92.23 v27.33,92.23
EINGANG1
  Top 0.4: U1.23 80.93,70.23 81.33,70.63 81.33,72.83 81.13,73.03 R26.2 R25.1
EINGANG2
  Top 0.4: U1.12 85.63,59.43 87.23,57.83 90.33,57.83 | 90.33,57.83 R46.1 | R47.2 90.33,57.83
EINGANG3  (via drill 0.4 pad 0.8)
  Top 0.25: U1.8 78.53,56.43 78.73,56.23 78.73,50.13 R48.2 77.73,48.73 R49.2 78.23,47.93 77.63,47.33 77.63,35.03 v77.33,34.73
  Bottom 0.25: v77.33,34.73 79.03,34.73 79.63,34.73 80.88,33.48 JP2.2
EINGANG5
  Top 0.25: U1.3 74.53,54.13 | 74.53,54.13 74.53,49.83 73.63,48.93 JP1.2 | 74.53,54.13 R11.1 R10.1
GND  (via drill 0.4 pad 0.8)
  Top 0.25: C23.1 v73.13,18.63 | R5.1 v75.13,27.23 | v75.33,59.43 U1.4 | C13.1 v77.73,52.83 R48.1 | U2.19 44.58,65.38 v44.53,65.43 | U2.27 47.58,66.68 v47.53,66.63 | U2.31 47.68,68.68 v47.53,68.43 | C12.1 v78.53,73.63 | 86.52,63.43 C10.1 | C75.1 v33.93,73.63 | U18.2 v31.13,73.83 | C76.1 28.33,69.93 28.03,69.63 v27.23,69.63 | v35.93,74.03 C8.1 | v22.93,44.63 C18.1 24.87,45.24 U4.15 | C16.1 v14.93,46.03 | v14.93,56.63 C15.1 | U12.3 v49.13,50.63 | 44.28,75.62 C7.1 44.08,75.63 | v34.73,65.23 Q1.2 | U2.7 38.38,68.18 v38.13,68.43 | R10.2 v71.03,54.13 | v43.43,75.23 43.43,75.63 44.08,75.63 | 44.08,75.63 U2.43 | C35.1 v30.73,88.23 | C34.1 v30.73,90.23 | C36.1 v30.73,92.23 | U7.4 36.3,98.63 v37.13,98.63 | U7.5 36.3,103.83 v37.13,103.83 | U7.8 34.35,103.83 v33.53,103.83 | U14.6 144.93,59.23 v145.73,59.23 146.73,60.23 C60.1
  Top 0.3: C6.1 68.07,67.83 v67.13,67.83 | v80.93,63.63 81.13,63.43 U1.17 86.33,63.43 | U1.25 79.33,67.03 v79.53,66.83 | v92.73,62.63 U16.2 88.33,62.63 87.53,63.43 86.52,63.43 | U9.4 136.13,28.51 v136.13,28.83 | U9.5 129.23,28.51 v129.23,28.83 128.93,29.13 R51.1 | U9.8 129.23,26.55 v129.23,26.13 | v130.43,22.73 C50.1 | C59.1 v139.13,57.03 | C58.1 v139.13,58.63 | v135.53,56.03 R57.1
  Top 0.4: C11.1 v95.83,60.23 | C26.2 v15.13,132.63 | C27.1 v24.13,133.43 | R16.1 v26.13,133.43 | v24.13,127.03 C24.1 | v27.73,126.03 C25.1 | v26.13,126.63 R15.1 | v39.13,134.03 C22.1 | R66.1 107.73,21.43 108.53,21.43 v108.53,20.43 | T1.2 37.27,121.89 v37.33,121.83 | T2.2 37.27,106.29 v37.33,106.23 | R22.1 v48.13,96.23 | v52.53,97.03 R24.2 | v51.53,88.03 C33.1 | C32.1 v44.33,90.83 | C39.1 v29.33,103.63 | R34.1 v145.13,37.63 | R36.1 141.63,36.62 v141.63,37.63 | L5.1 v137.93,38.93 | R38.1 v135.63,39.33 | v127.83,37.73 R45.2 | v85.53,57.23 85.43,57.23 | C48.1 v127.33,44.83 | C47.1 v134.73,44.43 | v132.33,19.03 R53.1
  Top 0.5: C4.1 v28.53,4.63 | C3.1 v28.53,8.83 | C2.1 v28.53,12.43 | v28.73,26.63 C5.2 | R4.1 v35.33,25.43 | U17.7 34.33,23.63 v34.93,23.63 35.6,23.63 U17.6 | U17.2 34.33,14.63 v34.93,14.63 35.6,14.63 U17.3 | U15.5 70.47,133.09 69.93,133.63 63.53,133.63 v63.53,132.83 C44.1 | v54.33,121.63 C29.1 | v53.73,105.83 L4.2 | v112.23,46.23 C43.1 | U11.3 16.23,76.41 C17.2
  Top 0.6: C19.1 73.13,16.82 v73.13,18.63 | v129.73,49.33 127.73,51.33 v91.43,51.33 v85.53,57.23 | v133.53,49.43 133.53,50.03 129.03,54.53 93.43,54.53 92.13,55.83 v92.13,56.53 | v46.03,85.23 46.03,83.83 v48.73,81.13 v61.93,81.13 v66.43,76.63 v78.43,76.63 | v50.33,84.03 63.03,84.03 v67.83,79.23 79.73,79.23 82.03,76.93 v82.03,74.83
  Top 0.8: 108.53,5.63 U13.6 | 108.53,5.63 v101.93,5.63 | v115.33,5.63 108.53,5.63 | v119.73,27.43 117.63,27.43 VD2.A 117.63,21.83 v119.73,21.83 | C53.1 v116.93,12.63 | v108.53,20.43 U13.3 | v105.18,20.43 U13.5 | C57.1 v117.53,40.43 | D4.1 119.59,44.63 v119.53,44.63 | 91.93,27.63 v88.73,27.63 | 91.93,27.63 C55.2 | 91.93,27.63 v94.93,27.63 97.93,27.63 C28.2 100.13,27.73 v100.13,26.43 | C17.2 v14.03,82.23 | C52.2 v124.33,5.03 | C54.2 v144.93,5.23
  Top 1: VD1.MI 83.07,109.29 v83.13,109.23 | v92.13,56.53 92.13,56.63
  Bottom 0.25: v73.13,18.63 72.93,18.63 | v75.13,27.23 75.13,26.83 | v75.33,59.43 75.33,59.83 | v77.73,52.83 77.73,52.43 | v67.13,67.83 66.93,67.83 | v44.53,65.43 44.53,65.63 | v47.53,66.63 47.53,66.43 | v47.53,68.43 47.13,68.43 | v80.93,63.63 80.93,63.83 | v78.53,73.63 78.53,73.83 | v92.73,62.63 93.13,62.63 | v95.83,60.23 96.63,60.23 | v33.93,73.63 33.93,73.83 | v27.23,69.63 27.23,69.03 | 35.93,74.23 v35.93,74.03 | v22.93,44.63 22.73,44.63 | v14.93,46.03 14.93,45.83 | v14.93,56.63 14.93,56.83 | v49.13,50.63 48.33,50.63 | v34.73,65.23 34.93,65.23 | v38.13,68.43 37.73,68.43 | v43.43,75.23 43.13,75.23 | v71.03,54.13 70.83,54.13 | v30.73,88.23 30.93,88.23 | v30.73,90.23 30.93,90.23 | v30.73,92.23 30.93,92.23 | v37.13,98.63 37.53,98.63 | v37.13,103.83 37.33,103.83 | v33.53,103.83 33.33,103.83 | v129.73,49.33 129.73,46.03 U8.GND 133.53,47.03 v133.53,49.43
  Bottom 0.3: v79.53,66.83 79.53,66.63 | v108.53,20.43 v105.18,20.43 | v136.13,28.83 136.13,29.13 | v129.23,28.83 129.23,29.03 | v129.23,26.13 129.23,26.03 | 130.23,22.73 v130.43,22.73 | v145.73,59.23 146.13,59.23 | v139.13,57.03 138.93,57.03 | v139.13,58.63 138.93,58.63
  Bottom 0.4: v15.13,132.63 14.53,132.63 | v24.13,133.43 24.13,133.63 | v26.13,133.43 26.13,133.63 | v24.13,127.03 24.13,126.83 | v27.73,126.03 27.13,126.03 | v26.13,126.63 26.13,126.83 | 38.93,134.03 v39.13,134.03 | 54.13,121.63 v54.33,121.63 | v37.33,121.83 37.33,121.43 | v37.33,106.23 37.33,105.83 | v53.73,105.83 53.33,105.83 | v48.13,96.23 48.13,95.83 | v52.53,97.03 53.13,97.03 | v51.53,88.03 51.53,88.83 | v44.33,90.83 44.33,90.43 | v29.33,103.63 29.33,104.03 | v145.13,37.63 145.13,37.83 | v141.63,37.63 141.63,37.83 | v137.93,38.93 137.93,39.13 | v135.63,39.33 135.83,39.33 | v127.83,37.73 127.43,37.73 | v127.33,44.83 127.33,44.63 | v134.73,44.43 134.73,44.63 | v132.33,19.03 132.13,19.03
  Bottom 0.5: v28.53,4.63 28.33,4.63 | v28.53,8.83 28.13,8.83 | v28.53,12.43 28.33,12.43 | v28.73,26.63 28.73,27.23 | v35.33,25.43 35.33,25.23 | v34.93,23.63 34.93,24.03 | v34.93,14.63 34.93,14.23 | v112.23,46.23 111.53,46.23 | v63.53,132.83 63.53,133.03 | v14.03,82.23 13.53,82.23
  Bottom 0.6: v85.53,57.23 85.53,56.73
  Bottom 0.8: v116.93,12.63 116.93,12.03 | v117.53,40.43 117.53,40.23 | v119.53,44.63 119.13,44.63 | v88.73,27.63 88.73,27.43 88.33,27.43 88.33,27.63 | v94.93,27.63 94.53,27.63 | v124.33,5.03 124.33,4.43 | v144.93,5.23 144.93,4.63
  Bottom 1: v83.13,109.23 83.13,108.43
  other vias: 33.53,130.03 47.93,90.03 131.13,44.63 46.03,83.93 54.23,81.13 57.03,81.13 54.23,84.03 57.03,84.03 62.93,84.03 79.63,79.23 93.53,54.53 105.63,54.53 105.63,51.33 120.23,51.33 118.93,54.53 126.73,54.53 126.73,51.33
  pour Bottom (isolate 0.27): 1.13,137.23 73.13,137.03 73.13,126.03 95.13,126.03 102.13,119.03 102.13,96.03 102.13,94.03 102.13,89.03 117.13,74.03 163.13,74.03 163.13,1.03 91.13,1.03 91.13,12.03 73.13,12.03 73.13,1.03 1.13,1.03
ITDO
  Top 0.25: R43.1 R39.1 87.23,19.13 87.23,22.83 86.23,23.83 82.73,23.83 80.73,25.83 80.73,45.83 81.73,46.83 81.73,58.63 81.03,59.33 81.03,61.33 79.73,62.63 79.73,65.43 80.53,66.23 80.53,67.23 80.13,67.63 U1.24
KONTRAST  (via drill 0.4 pad 0.8)
  Top 0.25: X1.17 58.61,50.11 57.83,49.33 57.83,39.73 57.13,39.03 56.33,39.03 44.63,39.03 39.83,43.83 29.93,43.83 v29.53,44.23 | R37.3 8.13,9.83 9.93,11.63 9.93,14.03 5.53,18.43 5.53,36.23 10.73,41.43 29.13,41.43 v29.53,41.03
  Bottom 0.25: v29.53,44.23 v29.53,41.03
LOGIK1
  Top 0.25: U1.30 75.33,71.03 72.13,74.23 64.93,74.23 61.33,77.83 47.13,77.83 46.13,78.83 R33.1 42.13,78.83 41.58,78.28 U2.48
LOGIK2
  Top 0.25: U1.28 76.93,71.63 73.13,75.43 65.73,75.43 62.13,79.03 49.13,79.03 45.93,82.23 41.53,82.23 37.93,78.63 37.93,71.03 38.28,70.68 U2.2
MATCH_MAT0.2
  Top 0.25: U1.32 73.73,70.43 71.13,73.03 64.13,73.03 60.53,76.63 43.33,76.63 42.58,75.88 U2.46
N$1
  Top 1: TR1.3 TR1.2
N$2
  Top 1: F1.2 F1.2A 119.65,127.71 126.23,121.13 TR1.1
N$3
  Top 1: F1.1A F1.1 X2.1
N$4
  Top 1: X3.1 151.33,128.63 149.13,126.43 145.53,126.43 141.93,122.83 141.93,103.03 144.03,100.93 BU1.2
N$5
  Top 1: BU1.1 141.83,92.33 135.63,86.13 TR1.4
N$6
  Top 1: TR1.7 91.93,101.13 91.93,116.13 | 91.93,116.13 TR1.5 | VD1.AC2 77.99,116.13 91.93,116.13
N$7
  Top 1: TR1.8 100.93,91.13 100.93,106.13 | 100.93,106.13 TR1.6 | VD1.AC1 83.07,120.43 98.53,120.43 100.93,118.03 100.93,106.13
N$8
  Top 0.25: U2.26 51.38,66.18 R9.2
N$9
  Top 0.5: L1.1 36.2,12.43 C2.2 33,16.23 U17.1
N$10
  Top 0.5: XG1.5 43.5,8.96 L1.2 33.13,8.96 C3.2
N$11
  Top 0.5: XG1.6 62.18,2.43 37.53,2.43 R1.1
N$12  (via drill 0.4 pad 0.8)
  Top 0.4: R13.2 37.73,36.23 | 37.73,36.23 R12.2 | 37.73,36.23 v36.33,36.23 | v20.33,12.83 17.79,10.29 R2.2
  Top 0.5: R1.2 C4.2 33,2.83 18.53,2.83 17.79,3.57 R2.2
  Bottom 0.5: v36.33,36.23 32.93,36.23 20.33,23.63 v20.33,12.83
N$13
  Top 0.5: R2.3 21.79,4.63 25.93,4.63 27.93,6.63 38.93,6.63 40.93,4.63 46.13,4.63 48.04,6.54 XG1ALTER.1 48.04,16.12 46.38,17.78 XG1.4
N$14
  Top 0.5: U3.1 23.42,28.82 R3.1 R4.2
N$15
  Top 0.25: U2.12 36.98,65.68 35.13,63.83 32.03,63.83 Q1.3
N$16
  Top 0.25: U2.11 35.38,66.18 34.93,66.63 32.03,66.63 Q1.1
N$17
  Top 0.25: 86.37,61.68 C10.2 86.14,61.83
  Top 0.4: U16.5 86.37,61.68 | 86.14,61.83 U1.15
N$18
  Top 0.25: U4.1 26.14,58.77 C9.1
N$19
  Top 0.25: U4.4 22.33,59.1 C14.1
N$20
  Top 0.25: U4.6 19.79,53.49 18.73,52.43 15,52.43 C15.2
N$21
  Top 0.25: U4.2 24.87,54.37 20.6,50.1 C16.2
N$22
  Top 0.25: X4.5 33.26,53.23 29.03,53.23 23.6,47.8 U4.14
N$23
  Top 0.25: U4.3 23.6,59.17 C9.2
N$24
  Top 0.25: U4.5 21.06,57.7 20.53,58.23 20.53,58.83 19.93,59.43 C14.2
N$25
  Top 0.25: X4.6 28.87,54.37 22.33,47.83 U4.13
N$26
  Top 0.25: U7.6 35.65,102.22 C37.1
N$27
  Top 0.4: C20.2 X5.SIG
N$28
  Top 0.4: XG1ALTER.2 56.93,12.43 37.73,31.63 R12.1
N$29
  Top 0.4: C20.1 R14.2 R19.2
N$30
  Top 0.4: 20.93,129.43 R14.1 | 20.93,129.43 C26.1 | 20.93,129.43 22.19,129.43 C21.1 C24.2 24.13,129.23 R15.2 27.73,129.23 27.89,129.4 U5.3
N$31
  Top 0.4: C21.2 21.99,127.63 R19.1
N$32
  Top 0.4: U5.2 29.29,130.66 29.13,130.83 R17.2 R16.2 24.27,130.83 C27.2
N$33
  Top 0.4: U5.1 29.62,131.94 29.13,132.43 R17.1
N$34
  Top 0.5: U5.6 39.52,129.42 40.53,130.43 R18.2
N$35
  Top 0.5: REL1.8 46.53,129.63 45.73,130.43 R18.1
N$36
  Top 0.5: REL1.2 REL1.9
N$37
  Top 0.5: REL2.8 REL1.3
N$38
  Top 0.5: REL2.9 REL2.2
N$39
  Top 0.4: 55.33,125.5 L2.1
  Top 0.5: REL1.7 49.07,124.09 49.53,123.63 54.93,123.63 55.33,124.03 55.33,125.5
N$40
  Top 0.5: L2.2 C29.2 L3.2
N$41
  Top 0.4: 55.53,117.96 L3.1
  Top 0.5: REL1.4 49.07,119.17 49.53,119.63 54.93,119.63 55.33,119.23 55.53,117.96
N$42
  Top 0.4: 55.13,109.3 C30.2
  Top 0.5: REL2.7 49.07,108.69 49.73,108.03 54.93,108.03 55.13,108.23 55.13,109.3
N$43
  Top 0.4: 55.13,102.36 C31.2
  Top 0.5: REL2.4 49.07,102.97 49.73,103.63 54.93,103.63 55.13,103.43 55.13,102.36
N$44
  Top 0.5: C30.1 L4.1 C31.1
N$45
  Top 0.25: T1.1 35.39,121.02 R20.1
N$46
  Top 0.25: T2.1 35.39,107.62 R21.1
N$47
  Top 0.8: U13.2 110.21,24.63 VD2.K 110.33,24.63 L12.1 110.33,30.56 R70.2 R61.1
N$48
  Top 0.4: T2.3 41.45,109.45 REL2.10
N$49
  Top 0.4: T1.3 41.45,125.25 REL1.10
N$50
  Top 0.25: 46.53,96.63 39.73,96.63 | 39.73,96.63 C38.2 | C40.2 39.8,96.56 39.73,96.63
  Top 0.5: REL2.3 R22.2 46.53,96.63 46.53,95.83 47.29,95.06 U6.3
N$51
  Top 0.4: U6.1 49.83,93.53 49.93,93.63 51.13,93.63 51.53,94.03 R23.1
N$52
  Top 0.4: U6.2 48.56,94.47 49.33,95.23 R23.2 R24.1
N$53
  Top 0.6: R25.2 80.13,76.83 79.13,77.83 67.23,77.83 62.63,82.43 49.51,82.43 47.32,84.62 U6.6
N$54
  Top 0.25: U7.3 35.65,97.11 36.13,96.63 36.93,96.63 | 36.93,96.63 C38.1 | C40.1 36.86,96.56 36.93,96.63
N$55
  Top 0.4: X7.SIG 149.15,32.13 C41.2
N$56
  Top 0.4: R35.2 145.13,32.13 | 145.13,32.13 C41.1 | 145.13,32.13 R34.2
N$57
  Top 0.8: C42.2 D4.3
N$58  (via drill 0.4 pad 0.8)
  Top 0.5: D4.2 121.53,43.31 v121.53,46.23 C43.2 | v114.43,64.63 90.23,88.83 v89.53,88.83 | 67.93,128.83 U15.7 | 69.2,128.83 U15.6 | 69.2,128.83 67.93,128.83 | v71.33,122.83 69.2,124.96 U15.3 69.2,128.83 | 67.93,128.83 U15.2
  Bottom 0.5: v114.43,64.63 121.43,57.63 121.43,55.73 122.73,54.43 122.73,47.23 v121.53,46.23 | v89.53,88.83 89.93,89.23 89.93,111.23 81.13,120.03 74.73,120.03 71.93,122.83 v71.33,122.83
N$59
  Top 0.8: C42.1 R61.2
N$60
  Top 0.4: C45.2 141.53,32.13 | 141.53,32.13 R35.1 | 141.53,32.13 R36.2
N$61
  Top 0.3: C51.2 137.93,32.13
  Top 0.4: 137.93,32.13 C46.2 | 137.93,32.13 C45.1 | 137.93,32.13 L5.2
N$62
  Top 0.4: 131.76,39.43 131.76,34.5 134.13,32.13 C46.1 | 131.76,39.43 U8.3 | R38.2 131.87,39.33 131.76,39.43
N$63
  Top 0.4: U8.1 129.22,39.92 R44.1
N$64
  Top 0.4: U8.2 130.5,39.59 R44.2 R45.1
N$65
  Top 0.6: U8.6 131.74,49.62 128.53,52.83 92.33,52.83 90.33,54.83 R46.2
N$66
  Top 0.3: U9.7 127.13,27.2 R50.1
N$67
  Top 0.3: U9.6 131.41,27.86 131.64,27.62 C49.1
N$68
  Top 0.3: U9.3 137.44,27.86 137.93,28.34 137.93,28.63 C51.1
N$69
  Top 0.4: U10.1 137.02,19.03 | 137.02,19.03 R52.1 | 137.02,19.03 R53.2
N$70
  Top 0.25: U14.3 143.93,56.03 144.53,56.63
  Top 0.3: X8.4 154.93,59.23 154.13,60.03 149.73,60.03 146.33,56.63 144.53,56.63
N$71
  Top 0.25: U14.4 144.43,55.53 144.73,55.83
  Top 0.3: X8.3 154.93,54.03 154.13,53.23 149.73,53.23 147.13,55.83 144.73,55.83
N$72
  Top 0.25: R54.1 U14.5
N$73
  Top 0.25: 143.43,51.93 U14.2
  Top 0.3: R54.2 143.43,51.93
N$74
  Top 0.8: C57.2 R70.1
N$75
  Top 0.4: U13.4 106.85,20.51 106.13,21.23 R66.2 R65.1 104.53,24.69 C56.1
N$77
  Top 0.25: 144.43,61.13 U14.7
  Top 0.3: 144.43,61.13 143.33,62.23 97.13,62.23 92.73,66.63 87.93,66.63 87.13,67.43 R55.1
N$78
  Top 0.25: C58.2 U14.10
  Top 0.3: C58.2 141.39,59.37 140.93,59.83 137.73,59.83 137.33,59.43 R56.1 R57.2
N$79
  Top 0.25: 143.93,60.63 U14.8
  Top 0.3: 143.93,60.63 143.13,61.43 96.73,61.43 92.33,65.83 R55.2 U1.20
N$80
  Top 0.25: X8.5 159.23,55.13 161.53,57.43 161.53,61.63 160.33,62.83 150.33,62.83 149.53,63.63 R58.2
OUT
  Top 0.5: R3.2 32.53,24.63 33.06,24.1 U17.8 33.06,20.03 28.73,20.03 C5.1 21.13,18.13 U3.3
PEGEL1  (via drill 0.4 pad 0.8)
  Top 0.25: U2.32 47.98,69.18 47.53,69.63 v47.53,70.83 | v37.13,79.63 36.53,79.63 34.93,81.23 34.93,92.03 30.53,96.43 29.13,96.43 27.73,97.83 27.73,103.83 29.33,105.43 34.33,105.43 35,104.75 U7.7
  Bottom 0.25: v47.53,70.83 47.53,71.43 46.33,72.63 44.33,72.63 37.33,79.63 v37.13,79.63
PEGEL2  (via drill 0.4 pad 0.8)
  Top 0.25: U2.33 50.28,69.68 51.23,68.73 54.23,68.73 v55.23,69.73 | v110.73,64.73 89.83,85.63 88.53,85.63 85.13,89.03 57.83,89.03 55.23,86.43 v55.23,85.33
  Top 0.3: R50.2 127.33,29.03 R51.2 127.33,32.23 125.93,33.63 v125.93,42.93
  Bottom 0.25: v125.93,42.93 125.53,43.33 125.53,58.83 118.53,65.83 111.83,65.83 v110.73,64.73 | v55.23,85.33 v55.23,69.73
PEGEL3  (via drill 0.4 pad 0.8)
  Top 0.25: U2.38 46.58,74.08 46.93,74.43 49.53,74.43 50.73,73.23 55.13,73.23 v56.13,74.23 | v56.93,85.43 63.13,85.43 68.13,80.43 93.93,80.43 109.53,64.83 109.53,64.23 110.13,63.63 R58.1 C60.2
  Bottom 0.25: v56.13,74.23 56.13,75.23 55.93,75.43 55.93,84.83 56.53,85.43 v56.93,85.43
PROG_RELAIS2  (via drill 0.4 pad 0.8)
  Top 0.25: R7.1 v41.93,51.83 v41.93,60.03 | U2.44 43.58,71.08 v43.13,70.63 | v35.33,78.43 35.33,78.83 33.73,80.43 33.73,91.23 29.73,95.23 28.33,95.23 26.13,97.43 26.13,108.23 27.13,109.23 32.53,109.23 35.33,112.03 R20.2
  Bottom 0.25: v41.93,60.03 42.53,60.63 42.53,65.03 41.53,66.03 41.53,66.83 43.13,68.43 v43.13,70.63 43.13,71.43 41.13,73.43 39.13,73.43 38.53,74.03 38.53,74.63 37.73,75.43 32.73,75.43 30.93,77.23 30.93,78.63 31.53,79.23 34.93,79.23 35.33,78.83 v35.33,78.43 | X4.2 33.1,50.53 36.43,50.53 37.73,51.83 v41.93,51.83
RD  (via drill 0.4 pad 0.8)
  Top 0.25: X1.9 64.37,60.27 65.13,61.03 U1.42 | v57.13,71.83 55.53,71.83 54.88,71.18 U2.36
  Bottom 0.25: X1.9 57.69,60.27 57.13,60.83 v57.13,71.83
REF10MHZ
  Top 0.25: R5.2 75.13,30.28
  Top 0.3: 75.13,30.28 66.33,30.28 65.82,30.28 | 65.82,30.28 XG1.1 | U1.5 76.13,56.63 75.53,56.03 75.53,32.23 75.13,31.83 R5.2 | 65.82,30.28 XG1ALTER.4
REFCOUNT_CAP1.2
  Top 0.25: U1.31 74.53,70.83 71.73,73.63 64.53,73.63 60.93,77.23 44.93,77.23 | U2.47 42.08,76.38 42.93,77.23 44.93,77.23 | 44.93,77.23 R31.1
REFMATCH_MAT1.2
  Top 0.25: U2.1 38.78,71.18 38.53,71.43 38.53,78.43 41.73,81.63 45.53,81.63 48.73,78.43 61.73,78.43 65.33,74.83 72.73,74.83 76.13,71.43 U1.29
RELAIS1
  Top 0.25: U2.3 37.98,70.18 37.33,70.83 37.33,77.83 34.33,80.83 34.33,91.63 30.13,95.83 28.73,95.83 26.93,97.63 26.93,106.63 27.93,107.63 R21.2
RESET  (via drill 0.4 pad 0.8)
  Top 0.25: v42.43,50.53 44.93,50.53 45.63,50.53 46.13,51.03 R8.1 R6.2
  Bottom 0.25: X4.1 36.19,49.29 37.43,50.53 v42.43,50.53
RXD  (via drill 0.4 pad 0.8)
  Top 0.25: v35.23,56.23 29.33,56.23 21.06,47.96 U4.12 | U2.14 42.08,61.48 41.03,60.43 41.03,56.93 40.33,56.23 v38.73,56.23
  Bottom 0.25: v38.73,56.23 v35.23,56.23
TCK
  Top 0.25: 80.93,21.23 JP3.3 | 80.93,21.23 R41.1 | U1.11 80.93,47.13 79.93,46.13 79.93,25.23 80.93,24.23 80.93,21.23
TDI
  Top 0.25: JP3.2 | JP3.2 R40.1 | U1.9 79.33,47.83 78.33,46.83 JP3.2
TDO
  Top 0.25: JP3.5 R39.2
TMS  (via drill 0.4 pad 0.8)
  Top 0.25: JP3.4 83.53,21.23 R42.1 | U1.10 80.13,47.53 79.13,46.53 79.13,24.23 v79.53,23.83
  Bottom 0.25: JP3.4 83.4,23.16 82.93,23.63 79.73,23.63 v79.53,23.83
TXD  (via drill 0.4 pad 0.8)
  Top 0.25: v33.93,57.53 29.43,57.53 19.79,47.89 U4.11 | U2.13 41.58,61.88 40.33,60.63 40.33,57.93 39.93,57.53 v38.73,57.53
  Bottom 0.25: v38.73,57.53 v33.93,57.53
UHF1  (via drill 0.4 pad 0.8)
  Top 0.25: v56.43,41.13 43.83,41.13 36.33,48.63 36.33,56.63 32.53,60.43 28.93,60.43 27.13,62.23 27.13,67.73 28.53,69.13 35.33,69.13 36.78,67.68 U2.8
  Bottom 0.25: JP2.5 56.46,41.1 v56.43,41.13
UHF2  (via drill 0.4 pad 0.8)
  Top 0.25: v55.63,42.13 55.33,41.83 44.23,41.83 37.03,49.03 37.03,56.93 32.83,61.13 29.23,61.13 27.83,62.53 27.83,67.53 28.83,68.53 35.03,68.53 36.38,67.18 U2.9
  Bottom 0.25: JP2.6 80.04,43.64 78.13,41.73 57.53,41.73 57.13,42.13 v55.63,42.13
UHF3  (via drill 0.4 pad 0.8)
  Top 0.25: v56.73,43.03 54.73,43.03 54.23,42.53 44.63,42.53 37.73,49.43 37.73,57.33 33.23,61.83 29.53,61.83 28.53,62.83 28.53,67.33 29.13,67.93 34.73,67.93 35.98,66.68 U2.10
  Bottom 0.25: JP2.7 81.68,46.18 77.93,42.43 58.13,42.43 57.53,43.03 v56.73,43.03
UHFA  (via drill 0.4 pad 0.8)
  Top 0.25: U2.34 52.18,70.18 v52.53,69.83 | v53.53,48.33 53.53,46.43 v55.83,44.13
  Bottom 0.25: JP2.8 83.32,48.72 77.73,43.13 58.53,43.13 57.53,44.13 v55.83,44.13 | v52.53,69.83 52.83,69.53 52.83,66.63 52.63,66.43 52.63,65.63 52.83,65.43 52.83,57.73 52.63,57.53 52.63,56.83 52.83,56.63 52.83,53.03 52.63,52.83 52.63,51.93 53.53,51.03 v53.53,48.33
VCORE1.8
  Top 0.25: U18.5 32.08,70.64 C75.2 34.93,70.63 35.58,69.98 35.93,69.63 36.38,69.18 U2.5
WR  (via drill 0.4 pad 0.8)
  Top 0.25: U1.43 65.53,60.23 64.3,59 X1.10 57.36,59 v56.93,59.43 | v56.33,72.63 47.08,72.63 U2.37
  Bottom 0.25: v56.93,59.43 56.33,60.03 v56.33,72.63

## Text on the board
Dimension: Hammond 1598C 180x155x52
Measures: Input1 1M/25p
